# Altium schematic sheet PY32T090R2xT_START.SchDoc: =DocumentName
size A3; Revision: V2.0; SheetNumber: 2; SheetTotal: 2
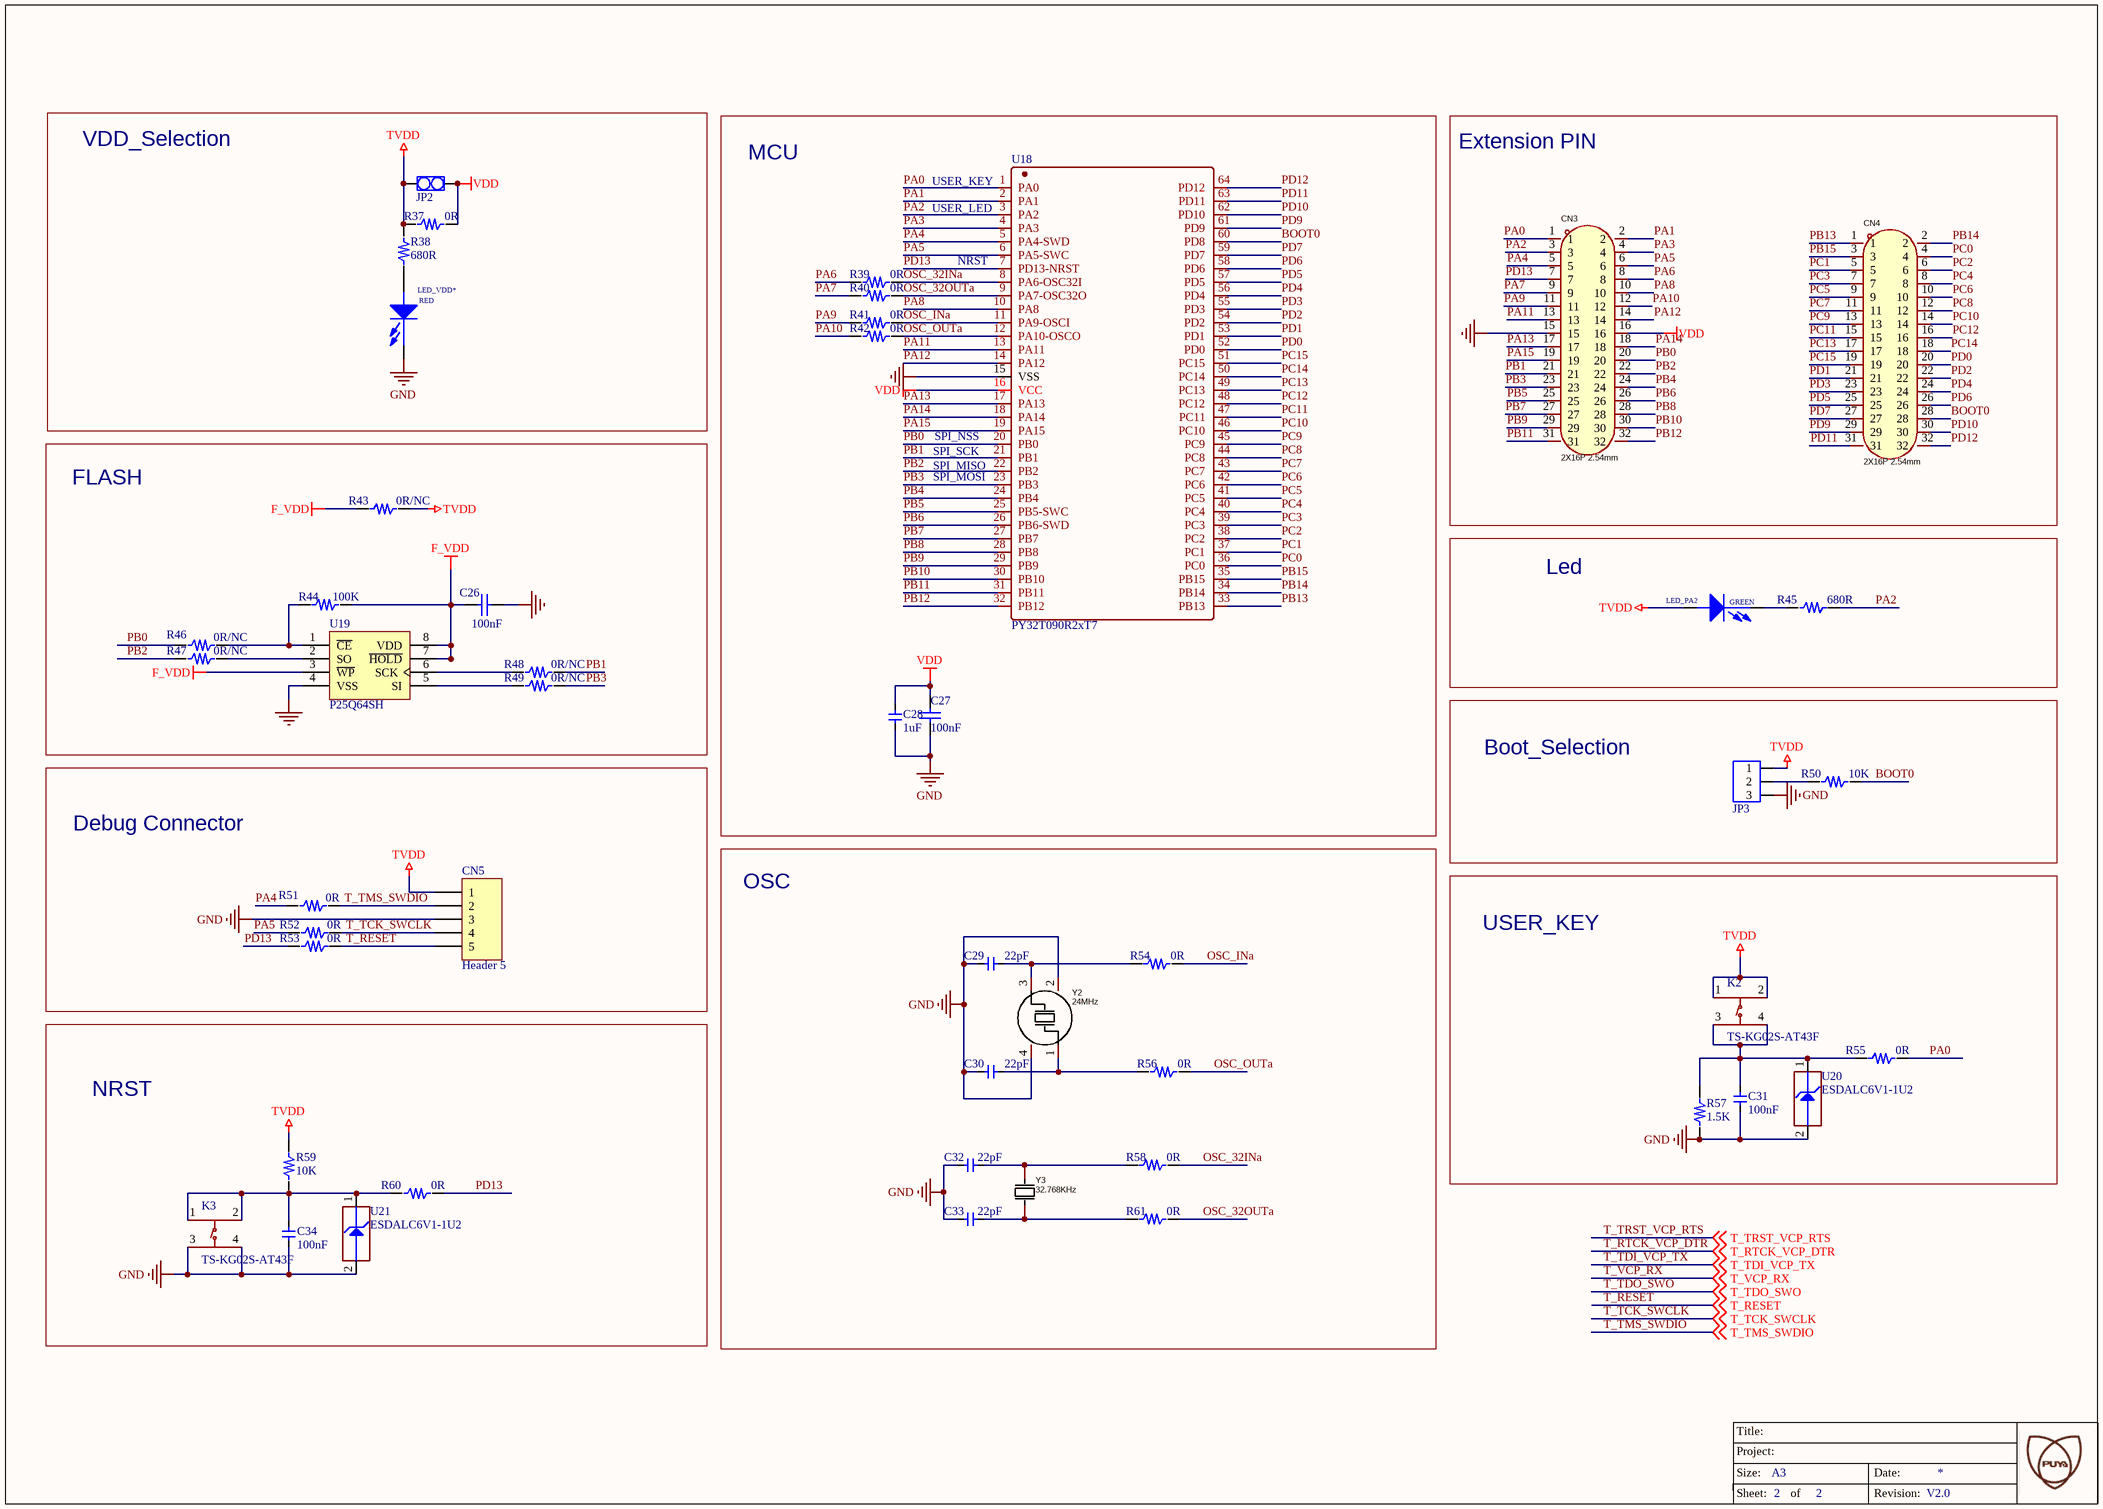
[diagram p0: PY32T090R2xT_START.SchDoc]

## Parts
C26  100nF  [C0603]
C27  100nF  [C0603]
C28  1uF  [C0603]
C29  22pF  [C0603]
C30  22pF  [C0603]
C31  100nF  [C0603]
C32  22pF  [C0603]
C33  22pF  [C0603]
C34  100nF  [C0603]
CN3  2X16P 2.54mm  [HDR-TH_32P-P2.54-V-M-R2-C16-S2.54-3]
CN4  2X16P 2.54mm  [HDR-TH_32P-P2.54-V-M-R2-C16-S2.54-3]
CN5  Header 5  [HDR1X5]
JP2  CON2  [CON2]  (value not drawn)
JP3  CON3  [CON3]  (value not drawn)
K2  TS-KG02S-AT43F  [SW-SMD_4P-L6.0-W6.0-P4.50-LS8.5]
K3  TS-KG02S-AT43F  [SW-SMD_4P-L6.0-W6.0-P4.50-LS8.5]
LED_PA2  GREEN  [0603_LED]
LED_VDD*  RED  [0603_LED]
R37  0R  [JP2_SMD]
R38  680R  [R0603]
R39  0R  [JP2_SMD]
R40  0R  [JP2_SMD]
R41  0R  [JP2_SMD]
R42  0R  [JP2_SMD]
R43  0R/NC  [JP2_SMD]
R44  100K  [R0603]
R45  680R  [R0603]
R46  0R/NC  [JP2_SMD]
R47  0R/NC  [JP2_SMD]
R48  0R/NC  [JP2_SMD]
R49  0R/NC  [JP2_SMD]
R50  10K  [R0603]
R51  0R  [JP2_SMD]
R52  0R  [JP2_SMD]
R53  0R  [JP2_SMD]
R54  0R  [JP2_SMD]
R55  0R  [JP2_SMD]
R56  0R  [JP2_SMD]
R57  1.5K  [R0603]
R58  0R  [JP2_SMD]
R59  10K  [R0603]
R60  0R  [JP2_SMD]
R61  0R  [JP2_SMD]
U18  PY32T090R2xT7  [LQFP-64_L10.0-W10.0-P0.50-LS12.0-BL]
U19  P25Q64SH  [SOP-8P]
U20  ESDALC6V1-1U2  [ESD_ST0201]
U21  ESDALC6V1-1U2  [ESD_ST0201]
Y2  24MHz  [CRYSTAL-SMD_4P-L3.2-W2.5-BL]
Y3  32.768KHz  [CRYSTAL-SMD_L3.2-W1.5-1]

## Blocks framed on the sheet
VDD_Selection: JP2 LED_VDD* R37 R38
MCU: C27 C28 R39-R42 U18
Extension PIN: CN3 CN4
FLASH: C26 R43 R44 R46-R49 U19
Led: LED_PA2 R45
Boot_Selection: JP3 R50
Debug Connector: CN5 R51-R53
OSC: C29 C30 C32 C33 R54 R56 R58 R61 Y2 Y3
USER_KEY: C31 K2 R55 R57 U20
NRST: C34 K3 R59 R60 U21

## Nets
F_VDD: C26.2 R43.2 R44.2 U19.3(~{WP}) U19.7(~{HOLD}) U19.8(VDD)
GND: C26.1 C27.1 C28.1 C29.1 C30.1 C31.1 C32.1 C33.1 C34.1 CN3.15 CN5.3 JP3.3 K3.3 K3.4 LED_VDD*.2(CATHODE) R57.1 U18.15(VSS) U19.4(VSS) U20.2(GND) U21.2(GND) Y2.2(GND) Y2.4(GND)
TVDD: CN5.1 JP2.1 JP3.1 K2.1 K2.2 LED_PA2.1(ANODE) R37.1 R38.2 R43.1 R59.1
VDD: C27.2 C28.2 CN3.16 JP2.2 R37.2 U18.16(VCC)
BOOT0: CN4.28 R50.2 U18.60(PD8)
OSC_32INa: R39.2 R58.2 U18.8(PA6-OSC32I)
OSC_32OUTa: R40.2 R61.2 U18.9(PA7-OSC32O)
OSC_INa: R41.2 R54.2 U18.11(PA9-OSCI)
OSC_OUTa: R42.2 R56.2 U18.12(PA10-OSCO)
PA0: CN3.1 R55.2 U18.1(PA0)
PA1: CN3.2 U18.2(PA1)
PA2: CN3.3 R45.2 U18.3(PA2)
PA3: CN3.4 U18.4(PA3)
PA4: CN3.5 R51.2 U18.5(PA4-SWD)
PA5: CN3.6 R52.2 U18.6(PA5-SWC)
PA6: CN3.8 R39.1
PA7: CN3.9 R40.1
PA8: CN3.10 U18.10(PA8)
PA9: CN3.11 R41.1
PA10: CN3.12 R42.1
PA11: CN3.13 U18.13(PA11)
PA12: CN3.14 U18.14(PA12)
PA13: CN3.17 U18.17(PA13)
PA14: CN3.18 U18.18(PA14)
PA15: CN3.19 U18.19(PA15)
PB0: CN3.20 R46.2 U18.20(PB0)
PB1: CN3.21 R48.1 U18.21(PB1)
PB2: CN3.22 R47.2 U18.22(PB2)
PB3: CN3.23 R49.1 U18.23(PB3)
PB4: CN3.24 U18.24(PB4)
PB5: CN3.25 U18.25(PB5-SWC)
PB6: CN3.26 U18.26(PB6-SWD)
PB7: CN3.27 U18.27(PB7)
PB8: CN3.28 U18.28(PB8)
PB9: CN3.29 U18.29(PB9)
PB10: CN3.30 U18.30(PB10)
PB11: CN3.31 U18.31(PB11)
PB12: CN3.32 U18.32(PB12)
PB13: CN4.1 U18.33(PB13)
PB14: CN4.2 U18.34(PB14)
PB15: CN4.3 U18.35(PB15)
PC0: CN4.4 U18.36(PC0)
PC1: CN4.5 U18.37(PC1)
PC2: CN4.6 U18.38(PC2)
PC3: CN4.7 U18.39(PC3)
PC4: CN4.8 U18.40(PC4)
PC5: CN4.9 U18.41(PC5)
PC6: CN4.10 U18.42(PC6)
PC7: CN4.11 U18.43(PC7)
PC8: CN4.12 U18.44(PC8)
PC9: CN4.13 U18.45(PC9)
PC10: CN4.14 U18.46(PC10)
PC11: CN4.15 U18.47(PC11)
PC12: CN4.16 U18.48(PC12)
PC13: CN4.17 U18.49(PC13)
PC14: CN4.18 U18.50(PC14)
PC15: CN4.19 U18.51(PC15)
PD0: CN4.20 U18.52(PD0)
PD1: CN4.21 U18.53(PD1)
PD2: CN4.22 U18.54(PD2)
PD3: CN4.23 U18.55(PD3)
PD4: CN4.24 U18.56(PD4)
PD5: CN4.25 U18.57(PD5)
PD6: CN4.26 U18.58(PD6)
PD7: CN4.27 U18.59(PD7)
PD9: CN4.29 U18.61(PD9)
PD10: CN4.30 U18.62(PD10)
PD11: CN4.31 U18.63(PD11)
PD12: CN4.32 U18.64(PD12)
PD13: CN3.7 R53.2 R60.2 U18.7(PD13-NRST)
T_RESET: CN5.5 R53.1 ; off-sheet T_RESET
T_TCK_SWCLK: CN5.4 R52.1 ; off-sheet T_TCK_SWCLK
T_TMS_SWDIO: CN5.2 R51.1 ; off-sheet T_TMS_SWDIO
NetC29_2: C29.2 R54.1 Y2.3(OSC2)
NetC30_2: C30.2 R56.1 Y2.1(OSC1)
NetC31_2: C31.2 K2.3 K2.4 R55.1 R57.2 U20.1(IO1)
NetC32_2: C32.2 R58.1 Y3.2(OSC2)
NetC33_2: C33.2 R61.1 Y3.1(OSC1)
NetC34_2: C34.2 K3.1 K3.2 R59.2 R60.1 U21.1(IO1)
NetJP3_2: JP3.2 R50.1
NetLED_PA2_2: LED_PA2.2(CATHODE) R45.1
NetLED_VDD*_1: LED_VDD*.1(ANODE) R38.1
NetR44_1: R44.1 R46.1 U19.1(~{CE})
NetR47_1: R47.1 U19.2(SO)
NetR48_2: R48.2 U19.6(SCK)
NetR49_2: R49.2 U19.5(SI)

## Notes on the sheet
- (near U18) USER_LED
- (near U18) USER_KEY
- (near U18) NRST
- (near U18) SPI_NSS
- (near U18) SPI_SCK
- (near U18) SPI_MOSI
- (near U18) SPI_MISO

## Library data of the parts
C26 C27 = 贴片高压陶瓷电容: Capacitor (Semiconductor SIM Model); 器件封装(外观): 0603; Value: 104
C28 = C0805: PCB DECAL: 0805
C29-C34 = C0603: PCB DECAL: 0603
CN3 CN4 = 2X16P 2.54mm: Manufacturer: XKB Connection(中国星坤); Symbol: X6522WV-2X16H-C60D30-E80; Add into BOM: yes; Circluar Pins/Square Pins: 方针; Current Rating (Max): 3A; Voltage Rating (Max): 250V; Soldering Temperature(Max): 260℃
CN5 = Header 5: Header, 5-Pin
JP2 = CON2_DIP
K2 K3 = TS-KG02S-AT43F: Manufacturer: HANBO(汉博); Add into BOM: yes; Circuit: 单刀单掷; Actuator Style: 圆形按钮; Operating Force: 250gf; Switch Length: 6mm; Switch Height: 4.3mm; Strike Gundam: 不带; Contact Current: 50mA; Voltage Rating (DC): 12V; Insulation Resistance: 100MΩ; Actuator/Cap Color: 黑色; Pin Style: 鸥翼型
LED_PA2 LED_VDD* = PDI-E803_Dup1
R37-R61 = R0603: PCB DECAL: 0603
U18 = PY32F072x
U19 = SST25VF010: Value: SST25VF020B; 器件封装(外观): SOP8
U20 U21 = ESDALC6V1-1U2: ESD protection 6V1; Internal_Part_Number: MCD-00170; Part_Type: Diode; Manufacturer: STMICROELECTRONICS; ECCN_US: EAR99; ECCN_EU: NEC; Provided_By: Subcon; Initial_Board_Reference: MB1274
Y2 = ABM8AIG-24.000MHZ-82Z-T: ±20ppm , 12.5pF , T_use: -40°C~125°C; Manufacturer: ABRACON; Add into BOM: yes; External load capacitor: 8pF; Frequency Stability(Full temperature range): ±50ppm; Equivalent Series Resistance (ESR): 50Ω
Y3 = XKXGI-SUA-32.768K: ±20ppm , 12.5pF , T_use: -40°C~125°C; Manufacturer: YXC(扬兴晶振); Add into BOM: yes; Crystal Type: 贴片晶振; Frequency Stability(Full temperature range): ±30ppm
